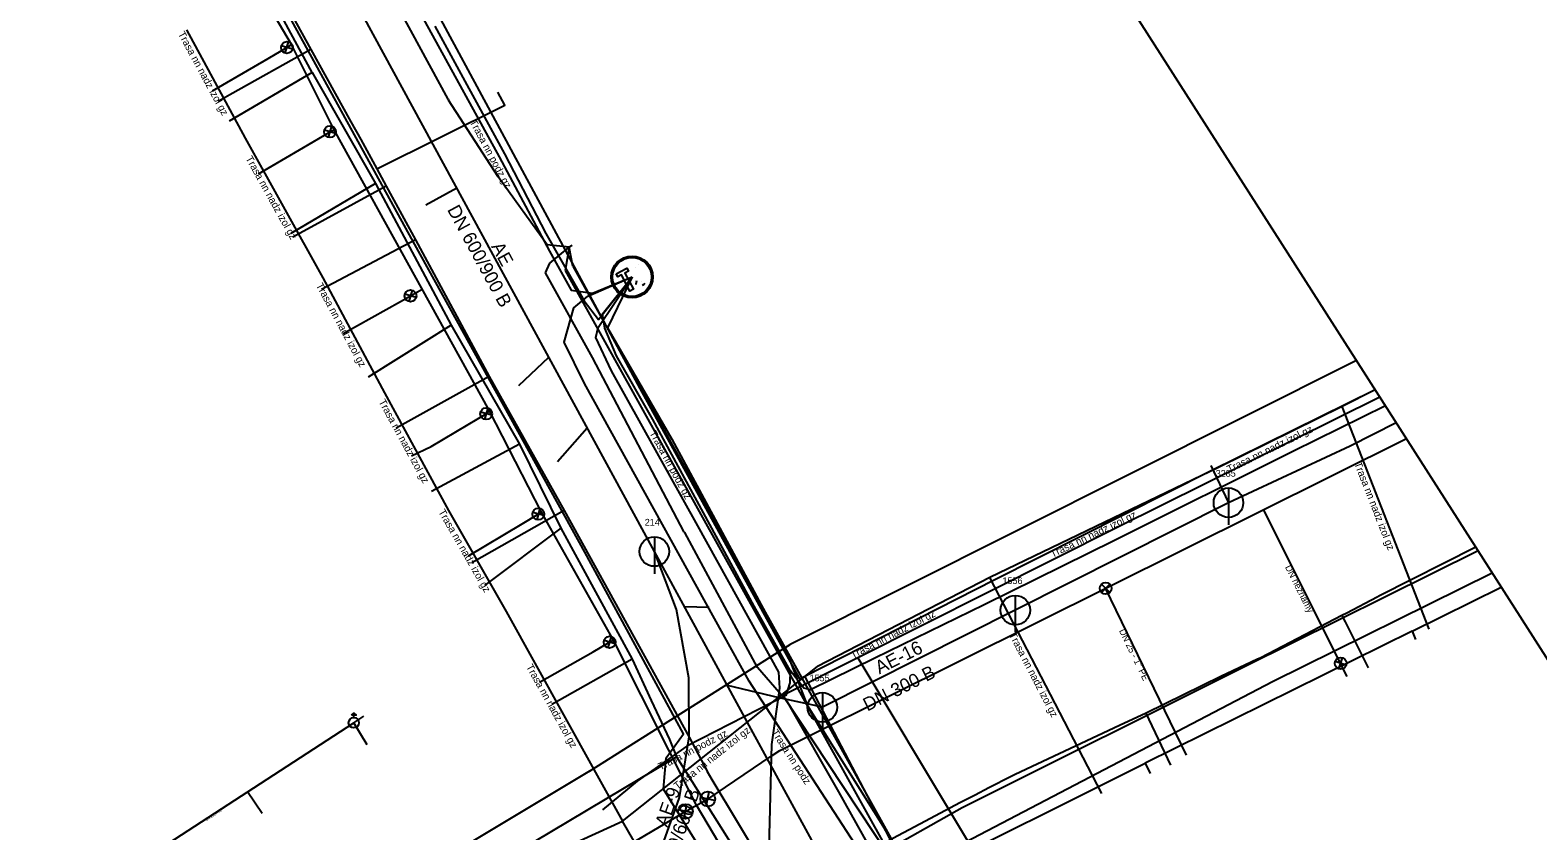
# Model space of a CAD drawing. Extents: x -493753 to -49291, y -1127285 to -112662.
# Drawn here: x -492897.5 to -492795.3, y -1126791 to -1126736.7 of the extents above; entities that cross this region are included whole.
import ezdxf

# ---------------------------------------------------------------- set-up
doc = ezdxf.new("R2010")
doc.units = 0
for name, color, linetype in [('Vrstva 1', 7, 'Continuous'), ('Vrstva 11', 7, 'Continuous'), ('Vrstva 15', 7, 'Continuous'), ('Vrstva 17', 7, 'Continuous'), ('Vrstva 19', 7, 'Continuous'), ('Vrstva 20', 7, 'Continuous'), ('Vrstva 22', 7, 'Continuous'), ('Vrstva 24', 7, 'Continuous'), ('Vrstva 26', 7, 'Continuous'), ('Vrstva 36', 7, 'Continuous'), ('Vrstva 37', 7, 'Continuous'), ('Vrstva 39', 7, 'Continuous'), ('Vrstva 5', 7, 'Continuous'), ('Vrstva 6', 7, 'Continuous'), ('Vrstva 8', 7, 'Continuous'), ('Vrstva 9', 7, 'Continuous')]:
    doc.layers.add(name, color=color, linetype=linetype)

# ---------------------------------------------------------------- blocks, each defined once
blk = doc.blocks.new('_UZAVE')
at = {"layer": 'Vrstva 1'}
for p, q in [((-0.035, -0.035), (0.035, 0.035)), ((0.035, -0.035), (-0.035, 0.035))]:
    blk.add_line(p, q, dxfattribs=at)
for radius in [0.05, 0.0025]:
    blk.add_circle((0, 0), radius, dxfattribs=at)
blk = doc.blocks.new('_UZAV0')
at = {"layer": 'Vrstva 1'}
for p, q in [((-0.035, -0.035), (0.035, 0.035)), ((0.035, -0.035), (-0.035, 0.035))]:
    blk.add_line(p, q, dxfattribs=at)
for radius in [0.05, 0.0025]:
    blk.add_circle((0, 0), radius, dxfattribs=at)
blk = doc.blocks.new('_SACHT')
at = {"layer": 'Vrstva 1'}
blk.add_line((0, 0.035), (0, 0.05), dxfattribs=at)
blk.add_lwpolyline([(-0.015000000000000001, 0.05), (0, 0.065), (0.015000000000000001, 0.05), (0.0025, 0.05)], close=True, dxfattribs=at)
blk.add_circle((0, 0), 0.035, dxfattribs=at)
blk = doc.blocks.new('_SACH0')
at = {"layer": 'Vrstva 1'}
blk.add_line((0, 0.05), (0, -0.075), dxfattribs=at)
blk.add_circle((0, 0), 0.05, dxfattribs=at)

msp = doc.modelspace()

# ---------------------------------------------------------------- linework, layer by layer
at = {"layer": 'Vrstva 1'}
for p, q in [((-492878.44, -1126738.04), (-492883.93000000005, -1126741.12)), ((-492883.93000000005, -1126741.12), (-492884.72000000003, -1126741.56)), ((-492875.73000000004, -1126742.95), (-492875.07, -1126744.1500000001)), ((-492873.34, -1126747.29), (-492879.66000000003, -1126750.75)), ((-492871.36000000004, -1126750.9300000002), (-492877.72000000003, -1126754.3)), ((-492866.38, -1126760.2), (-492872.67000000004, -1126763.7)), ((-492861.29000000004, -1126769.26), (-492867.55000000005, -1126772.82)), ((-492851.27, -1126787.5), (-492851.57, -1126786.98)), ((-492846.86000000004, -1126794.83), (-492851.27, -1126787.5))]:
    msp.add_line(p, q, dxfattribs=at)
for points in [[(-493753.1287883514, -1126773.6344166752), (-493540.8808095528, -1127284.8652782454), (-492737.61000000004, -1126868.6400000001), (-492950.39, -1126535.73)], [(-492937.42000000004, -1126630.24), (-492931.64, -1126641.3), (-492927.73000000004, -1126648.23), (-492923.99000000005, -1126654.85), (-492920.54000000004, -1126661.22), (-492918.14, -1126665.44), (-492916.71, -1126668.03), (-492912.53, -1126675.61), (-492909.26, -1126681.56), (-492909.12, -1126681.82), (-492904.44, -1126690.35), (-492900.54000000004, -1126697.23), (-492897.51, -1126702.99), (-492895.26, -1126707.27), (-492890.45, -1126716.07), (-492886.81, -1126722.78), (-492884.43000000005, -1126727.1600000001), (-492878.44, -1126738.04), (-492875.73000000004, -1126742.95)], [(-492873.98000000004, -1126746.1300000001), (-492865.30000000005, -1126741.81), (-492865.79000000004, -1126740.94)], [(-492875.07, -1126744.1500000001), (-492873.98000000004, -1126746.1300000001), (-492873.34, -1126747.29), (-492871.36000000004, -1126750.9300000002), (-492866.38, -1126760.2), (-492861.29000000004, -1126769.26), (-492852.83, -1126784.62), (-492851.57, -1126786.98)], [(-492799.5317394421, -1126771.7588726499), (-492806.05000000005, -1126775.05), (-492806.22000000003, -1126775.1400000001), (-492808.26, -1126776.22), (-492808.60000000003, -1126776.3900000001), (-492814.09, -1126779.24), (-492814.32, -1126779.34), (-492816.80000000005, -1126780.52), (-492821.87, -1126783), (-492823.68000000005, -1126783.84), (-492830.74000000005, -1126787.1400000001), (-492831.01, -1126787.28), (-492832.52, -1126788.06), (-492833.45, -1126788.55), (-492833.9, -1126788.78), (-492834.48000000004, -1126789.08), (-492836.47000000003, -1126790.12), (-492839.74000000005, -1126791.86)], [(-492808.60000000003, -1126776.3900000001), (-492808.39, -1126776.82), (-492806.83, -1126779.9300000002)], [(-492820.2, -1126786.52), (-492821.67000000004, -1126783.4300000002), (-492821.87, -1126783)]]:
    msp.add_lwpolyline(points, dxfattribs=at)
at = {"layer": 'Vrstva 11'}
for points in [[(-492848.73000000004, -1126797.53), (-492854.56, -1126788.1500000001), (-492854.38, -1126786.02), (-492853.2, -1126784.3900000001), (-492859.9, -1126772.1), (-492871.87, -1126750.4000000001), (-492886.74000000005, -1126723.34), (-492898.4, -1126701.86), (-492908, -1126684.26), (-492916.54000000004, -1126668.6500000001), (-492921.45, -1126660.08), (-492926.55000000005, -1126650.44), (-492932.03, -1126640.6), (-492935.80000000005, -1126632.8900000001)], [(-492806.0331657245, -1126761.5869118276), (-492823.79000000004, -1126770.4000000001), (-492841.39, -1126779.25)], [(-492799.37161551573, -1126772.0093983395), (-492815.12, -1126779.81), (-492834.32, -1126789.4100000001), (-492840.18000000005, -1126792.71), (-492846.28, -1126796.1500000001), (-492848.73000000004, -1126797.53)], [(-492841.39, -1126779.25), (-492846.47000000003, -1126781.81), (-492838.25, -1126794.22), (-492850.91000000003, -1126802.26), (-492877.11000000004, -1126819.04), (-492895.80000000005, -1126830.76), (-492895.54000000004, -1126831.19)], [(-492841.39, -1126779.25), (-492828.07, -1126801.46)]]:
    msp.add_lwpolyline(points, dxfattribs=at)
at = {"layer": 'Vrstva 15'}
for p, q in [((-492855.18000000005, -1126772.05), (-492876.57, -1126732.69)), ((-492870.67000000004, -1126748.56), (-492868.57, -1126747.4100000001)), ((-492864.36000000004, -1126760.8), (-492862.33, -1126758.8900000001)), ((-492861.75, -1126765.95), (-492859.74000000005, -1126763.6700000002)), ((-492817.49000000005, -1126766.21), (-492816.29000000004, -1126768.74)), ((-492816.29000000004, -1126768.74), (-492830.73000000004, -1126776.02)), ((-492848.75, -1126783.83), (-492855.18000000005, -1126772.05)), ((-492851.47000000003, -1126775.83), (-492853.13, -1126775.79)), ((-492830.73000000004, -1126776.02), (-492843.80000000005, -1126782.6)), ((-492891.84, -1126794.23), (-492875.54000000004, -1126783.6400000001)), ((-492875.54000000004, -1126783.6400000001), (-492874.86000000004, -1126783.2)), ((-492874.63, -1126785.1500000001), (-492875.54000000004, -1126783.6400000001)), ((-492841.63, -1126796.85), (-492848.75, -1126783.83)), ((-492881.74000000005, -1126789.79), (-492882.74000000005, -1126788.32))]:
    msp.add_line(p, q, dxfattribs=at)
for points in [[(-492804.924818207, -1126763.3210032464), (-492808.04000000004, -1126764.9000000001), (-492816.29000000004, -1126768.74)], [(-492864.02, -1126803.31), (-492860.16000000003, -1126800.21), (-492856.72000000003, -1126796.26), (-492854.76, -1126792.33), (-492853.47000000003, -1126788.71), (-492852.82, -1126784.59), (-492852.84, -1126780.6), (-492853.67000000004, -1126775.98), (-492855.18000000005, -1126772.05)], [(-492843.80000000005, -1126782.6), (-492846.73000000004, -1126781.95), (-492850.22000000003, -1126781.1300000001)]]:
    msp.add_lwpolyline(points, dxfattribs=at)
at = {"layer": 'Vrstva 20'}
for p, q in [((-492885.12, -1126740.85), (-492881.35000000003, -1126738.6500000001)), ((-492882, -1126746.47), (-492878.30000000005, -1126744.29)), ((-492876.26, -1126757.27), (-492872.38, -1126755.11)), ((-492808.25, -1126780.51), (-492813.91000000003, -1126769.21)), ((-492867.78, -1126772.34), (-492864.14, -1126770.1700000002)), ((-492819.13, -1126785.85), (-492824.61000000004, -1126774.54)), ((-492862.97000000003, -1126780.9000000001), (-492859.33, -1126778.83)), ((-492846.67000000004, -1126785.52), (-492844.52, -1126784.45)), ((-492851.56, -1126788.81), (-492847.26, -1126785.9000000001)), ((-492847.26, -1126785.9000000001), (-492846.67000000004, -1126785.52)), ((-492852.32, -1126789.23), (-492851.56, -1126788.81)), ((-492853.07, -1126789.6500000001), (-492852.32, -1126789.23))]:
    msp.add_line(p, q, dxfattribs=at)
for points in [[(-492852.32, -1126789.23), (-492857.95, -1126778.05), (-492862.82, -1126769.3900000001), (-492866.35000000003, -1126762.51), (-492876.86000000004, -1126743.48), (-492879.77, -1126737.71), (-492881.46, -1126734.83), (-492885.64, -1126727.1400000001), (-492890.48000000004, -1126718.6800000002), (-492890.54000000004, -1126718.22), (-492897.26, -1126705.96), (-492901.5, -1126698.34), (-492906.52, -1126690), (-492906.82, -1126689.4100000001), (-492911.08, -1126681.1), (-492913.41000000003, -1126677.49)], [(-492881.35000000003, -1126738.6500000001), (-492880.07, -1126737.9100000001), (-492879.77, -1126737.71)], [(-492878.30000000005, -1126744.29), (-492877.15, -1126743.61), (-492876.86000000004, -1126743.48)], [(-492872.38, -1126755.11), (-492871.7, -1126754.73), (-492870.9, -1126754.27)], [(-492867.80000000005, -1126763.44), (-492866.57, -1126762.71), (-492866.35000000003, -1126762.51)], [(-492871.63, -1126765.57), (-492870.30000000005, -1126764.9300000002), (-492867.80000000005, -1126763.44)], [(-492844.52, -1126784.45), (-492804.2382379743, -1126764.3952086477)], [(-492864.14, -1126770.1700000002), (-492863.04000000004, -1126769.51), (-492862.82, -1126769.3900000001)], [(-492859.33, -1126778.83), (-492858.21, -1126778.19), (-492857.95, -1126778.05)], [(-492970.22000000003, -1126863.36), (-492958.22000000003, -1126855.33), (-492945.51, -1126848.03), (-492940.77, -1126845.12), (-492925.74000000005, -1126835.49), (-492904.65, -1126823), (-492904.05000000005, -1126822.61), (-492887.33, -1126811.73), (-492869.75, -1126799.77), (-492856.71, -1126791.8), (-492853.07, -1126789.6500000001)], [(-492786.67934407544, -1126894.0659225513), (-492787.42000000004, -1126892.8800000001), (-492788.56, -1126891.12), (-492791.28, -1126887.34), (-492800.45, -1126872.1400000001), (-492806.36000000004, -1126863.49), (-492810.7, -1126856.3), (-492813.24000000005, -1126852.47), (-492818.85000000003, -1126843.1400000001), (-492822.10000000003, -1126837.71), (-492822.55000000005, -1126837.04), (-492834.77, -1126816.78), (-492843.12, -1126804.04), (-492846.14, -1126799.6600000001), (-492852.32, -1126789.23)]]:
    msp.add_lwpolyline(points, dxfattribs=at)
at = {"layer": 'Vrstva 26'}
for p, q in [((-492869.14, -1126741.4100000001), (-492877.07, -1126726.79)), ((-492869.14, -1126741.4100000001), (-492869.12, -1126741.47)), ((-492865.75, -1126746.6600000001), (-492869.12, -1126741.47)), ((-492862.44, -1126751.27), (-492865.75, -1126746.6600000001)), ((-492860.95, -1126751.44), (-492862.44, -1126751.27)), ((-492860.74000000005, -1126751.33), (-492860.95, -1126751.44)), ((-492862.25, -1126752.51), (-492860.95, -1126751.44)), ((-492860.95, -1126751.44), (-492861.22000000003, -1126753.01)), ((-492860.7, -1126752.71), (-492860.95, -1126751.44)), ((-492862.55000000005, -1126753.1600000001), (-492862.25, -1126752.51)), ((-492859.38, -1126758.9100000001), (-492862.55000000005, -1126753.1600000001)), ((-492861.22000000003, -1126753.01), (-492837.7, -1126795.29)), ((-492860.7, -1126752.71), (-492837.9, -1126793.7)), ((-492853.17000000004, -1126770.74), (-492859.38, -1126758.9100000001)), ((-492853.17000000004, -1126770.74), (-492853.12, -1126770.76)), ((-492848.2, -1126779.9100000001), (-492853.12, -1126770.76)), ((-492813.31, -1126780.85), (-492798.4254072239, -1126773.4898109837)), ((-492846.14, -1126782.27), (-492848.2, -1126779.9100000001)), ((-492837.9, -1126793.7), (-492813.31, -1126780.85)), ((-492842.69, -1126788.32), (-492846.14, -1126782.27)), ((-492836.75, -1126798.9000000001), (-492842.69, -1126788.32))]:
    msp.add_line(p, q, dxfattribs=at)
at = {"layer": 'Vrstva 36'}
msp.add_line((-492859.57, -1126786.9300000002), (-492845.99000000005, -1126778.34), dxfattribs=at)
at = {"layer": 'Vrstva 37'}
for p, q in [((-492807.6126526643, -1126759.115688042), (-492845.99000000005, -1126778.34)), ((-492859.57, -1126786.9300000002), (-492899.16000000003, -1126810.62))]:
    msp.add_line(p, q, dxfattribs=at)
at = {"layer": 'Vrstva 39'}
for points in [[(-492879.80000000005, -1126736.94), (-492882.71, -1126731.53)], [(-492872.11000000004, -1126731.46), (-492856.16000000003, -1126761), (-492845.35000000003, -1126780.6700000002), (-492844.99000000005, -1126780.49)], [(-492878.37, -1126739.61), (-492879.80000000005, -1126736.94)], [(-492878.37, -1126739.61), (-492883.98000000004, -1126742.8900000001)], [(-492878.37, -1126739.61), (-492874.08, -1126747.12)], [(-492874.08, -1126747.12), (-492879.80000000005, -1126750.5)], [(-492874.08, -1126747.12), (-492868.95, -1126756.71)], [(-492868.95, -1126756.71), (-492874.57, -1126760.24)], [(-492868.95, -1126756.71), (-492864.31, -1126764.78)], [(-492844.99000000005, -1126780.49), (-492832.11000000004, -1126773.94), (-492817.5, -1126766.59), (-492806.3601976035, -1126761.0752463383)], [(-492864.31, -1126764.78), (-492870.28, -1126767.99)], [(-492864.31, -1126764.78), (-492861.52, -1126770.46)], [(-492861.52, -1126770.46), (-492866.68000000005, -1126774.34)], [(-492861.52, -1126770.46), (-492856.69, -1126779.34)], [(-492803.85000000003, -1126777.45), (-492797.80753528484, -1126774.4565171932)], [(-492803.85000000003, -1126777.45), (-492821.94, -1126786.3900000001)], [(-492803.85000000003, -1126777.45), (-492803.62, -1126778.01)], [(-492856.69, -1126779.34), (-492862.13, -1126782.4000000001)], [(-492856.69, -1126779.34), (-492855.39, -1126782.1400000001)], [(-492837.75, -1126794.28), (-492844.99000000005, -1126780.49)], [(-492855.39, -1126782.1400000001), (-492854.16000000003, -1126784.79), (-492853.69, -1126785.96)], [(-492870.58, -1126796.02), (-492853.69, -1126785.96)], [(-492853.69, -1126785.96), (-492845.76, -1126798.53), (-492841.59, -1126804.98)], [(-492837.75, -1126794.28), (-492821.94, -1126786.3900000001)], [(-492821.94, -1126786.3900000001), (-492821.59, -1126787.09)]]:
    msp.add_lwpolyline(points, dxfattribs=at)
at = {"layer": 'Vrstva 5'}
for points in [[(-492872.37, -1126733.1400000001), (-492870.46, -1126736.6500000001), (-492865.7, -1126745.32), (-492862.28, -1126751.7), (-492860.81, -1126754.35), (-492859.38, -1126754.54), (-492856.69, -1126753.45)], [(-492886.87, -1126736.71), (-492882.91000000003, -1126744.04)], [(-492882.91000000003, -1126744.04), (-492877.64, -1126753.52)], [(-492877.64, -1126753.52), (-492873.46, -1126761.3)], [(-492863.25, -1126810.8800000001), (-492864.13, -1126809.3800000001), (-492840.13, -1126794.11), (-492848.76, -1126780.82), (-492859.92000000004, -1126760.6700000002), (-492861.29000000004, -1126757.87), (-492860.64, -1126755.54), (-492859.68000000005, -1126754.76), (-492856.69, -1126753.45)], [(-492845.99000000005, -1126780.1), (-492848.42000000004, -1126775.75), (-492855.28, -1126763.11), (-492857.74000000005, -1126758.79), (-492858.54000000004, -1126756.9200000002), (-492858.7, -1126755.94), (-492856.69, -1126753.45)], [(-492873.46, -1126761.3), (-492869.13, -1126769.26)], [(-492806.3447955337, -1126761.099344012), (-492808.58, -1126762.23)], [(-492805.6584604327, -1126762.1731658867), (-492811.88, -1126765.25), (-492824.02, -1126771.29), (-492832.84, -1126775.6500000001), (-492840.24000000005, -1126779.28), (-492844.61000000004, -1126781.4100000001), (-492845.05000000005, -1126781.31), (-492845.99000000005, -1126780.1)], [(-492808.58, -1126762.23), (-492816.93000000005, -1126766.34)], [(-492802.7, -1126777.31), (-492808.58, -1126762.23)], [(-492816.93000000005, -1126766.34), (-492832.46, -1126773.8)], [(-492869.13, -1126769.26), (-492865.21, -1126776.11)], [(-492832.46, -1126773.8), (-492844.12, -1126779.84)], [(-492824.87, -1126788.44), (-492832.46, -1126773.8)], [(-492865.21, -1126776.11), (-492857.33, -1126790.3)], [(-492857.33, -1126790.3), (-492844.12, -1126779.84)], [(-492845.99000000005, -1126780.1), (-492846.01, -1126780.95), (-492846.28, -1126781.8), (-492847.16000000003, -1126782.24), (-492852.99000000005, -1126785.24), (-492856.35000000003, -1126787.59), (-492858.69, -1126789.54)], [(-492873.51, -1126797.69), (-492857.33, -1126790.3)], [(-492850.08, -1126802.8800000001), (-492857.33, -1126790.3)]]:
    msp.add_lwpolyline(points, dxfattribs=at)
at = {"layer": 'Vrstva 6'}
for points in [[(-492870.04000000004, -1126736.47), (-492865.33, -1126745.11), (-492862.54000000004, -1126750.51), (-492859.93000000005, -1126755.07), (-492858.96, -1126756.34), (-492856.69, -1126753.45)], [(-492898.47000000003, -1126832.09), (-492886.41000000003, -1126824.24), (-492876.05000000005, -1126817.81), (-492860.04000000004, -1126807.6800000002), (-492849.41000000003, -1126801.1300000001), (-492848.23000000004, -1126800.02), (-492847.80000000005, -1126798.34), (-492847.4, -1126792.12), (-492847.23000000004, -1126785.11), (-492846.68000000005, -1126781.31), (-492846.74000000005, -1126780.22), (-492852.23000000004, -1126770.3), (-492858.08, -1126759.81), (-492859.14, -1126757.56), (-492858.99000000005, -1126756.8800000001), (-492856.69, -1126753.45)], [(-492856.69, -1126753.45), (-492858.36000000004, -1126756.9000000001), (-492854, -1126764.44), (-492846.25, -1126778.79), (-492844.82, -1126782.46), (-492836.75, -1126795.34), (-492826.22000000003, -1126812.12), (-492807.54000000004, -1126842.09), (-492794.08, -1126863.74), (-492778.1241839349, -1126889.6329544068)]]:
    msp.add_lwpolyline(points, dxfattribs=at)
at = {"layer": 'Vrstva 8'}
msp.add_lwpolyline([(-492857.76795837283, -1126753.2292562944), (-492857.0524047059, -1126752.8499103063), (-492856.938450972, -1126753.0648592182), (-492857.1761743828, -1126753.1908867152), (-492856.5989087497, -1126754.2797727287), (-492856.8335073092, -1126754.4041435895), (-492857.41077294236, -1126753.3152575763), (-492857.6540046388, -1126753.4442052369)], close=True, dxfattribs=at)
for points in [[(-492856.4899527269, -1126752.7947227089), (-492856.4874678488, -1126752.7934053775)], [(-492856.22951841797, -1126752.5834395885), (-492856.2334704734, -1126752.5759848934)], [(-492856.3875155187, -1126753.714502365), (-492856.44382650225, -1126753.9385358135), (-492856.43723975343, -1126753.950960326)], [(-492856.0444755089, -1126753.7491055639), (-492856.0544151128, -1126753.754374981)], [(-492855.9895033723, -1126753.996908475), (-492855.87037791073, -1126753.9273883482), (-492855.8125070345, -1126753.874425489)]]:
    msp.add_lwpolyline(points, dxfattribs=at)
for radius in [1.4115987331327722, 1.3204111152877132]:
    msp.add_circle((-492856.69, -1126753.45), radius, dxfattribs=at)

# ---------------------------------------------------------------- block references
at = {"layer": 'Vrstva 17'}
for name, p, xscale, yscale in [('_SACH0', (-492816.29000000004, -1126768.74), 19.997500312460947, 19.997500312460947), ('_SACH0', (-492855.18000000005, -1126772.05), 19.997500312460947, 19.997500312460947), ('_SACH0', (-492830.73000000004, -1126776.02), 19.997500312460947, 19.997500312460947), ('_SACH0', (-492843.80000000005, -1126782.6), 19.997500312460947, 19.997500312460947), ('_SACHT', (-492875.54000000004, -1126783.6400000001), 9.998750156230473, 9.998750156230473)]:
    msp.add_blockref(name, p, dxfattribs=dict(at, xscale=xscale, yscale=yscale))
at = {"layer": 'Vrstva 22'}
for name, p, xscale, yscale, rotation in [('_UZAV0', (-492880.07, -1126737.9100000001), 7.999000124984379, 7.999000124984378, 28.542533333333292), ('_UZAV0', (-492877.15, -1126743.61), 7.999000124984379, 7.999000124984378, 28.542533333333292), ('_UZAV0', (-492871.7, -1126754.73), 7.99900012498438, 7.999000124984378, 119.19454166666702), ('_UZAV0', (-492866.57, -1126762.71), 7.999000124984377, 7.999000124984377, 119.447713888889), ('_UZAV0', (-492863.04000000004, -1126769.51), 7.999000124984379, 7.999000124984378, 119.39408888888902), ('_UZAV0', (-492858.21, -1126778.19), 7.99900012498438, 7.999000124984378, 118.82552222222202), ('_UZAV0', (-492808.69, -1126779.62), 7.999000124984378, 7.999000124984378, 26.628288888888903), ('_UZAVE', (-492851.56, -1126788.81), 9.998750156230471, 9.998750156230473, 33.2741916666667), ('_UZAVE', (-492853.07, -1126789.6500000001), 9.998750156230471, 9.998750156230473, 33.2741916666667)]:
    msp.add_blockref(name, p, dxfattribs=dict(at, xscale=xscale, yscale=yscale, rotation=rotation))
at = {"layer": 'Vrstva 22', "xscale": 7.999000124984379, "yscale": 7.999000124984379}
msp.add_blockref('_UZAV0', (-492824.61000000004, -1126774.54), dxfattribs=at)

# ---------------------------------------------------------------- texts
at = {"layer": 'Vrstva 19'}
for s, height, rotation, p in [('DN 600/900 B', 0.9098880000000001, 298.5275916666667, (-492869.238, -1126748.886)), ('AE', 0.9098880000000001, 298.5275916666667, (-492866.25600000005, -1126751.385)), ('AE-16', 0.9098880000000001, 26.74140277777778, (-492839.939, -1126780.3760000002)), ('DN 300 B', 0.9098880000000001, 26.74140277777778, (-492840.75100000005, -1126782.8900000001)), ('DN 500/600 B', 0.9098880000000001, 70.41438611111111, (-492854.639, -1126795.5150000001)), ('AE-9', 0.9098880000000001, 70.41438611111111, (-492854.30500000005, -1126790.764)), ('DN 200 PVC', 0.16049400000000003, 33.01069444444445, (-492885.50700000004, -1126790.306))]:
    msp.add_text(s, height=height, rotation=rotation, dxfattribs=at).set_placement(p)
for s, p in [('3285', (-492817.152, -1126766.98)), ('214', (-492855.829, -1126770.29)), ('1556', (-492831.59300000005, -1126774.25)), ('1555', (-492844.663, -1126780.84))]:
    msp.add_text(s, height=0.45494400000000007, dxfattribs=at).set_placement(p)
at = {"layer": 'Vrstva 24'}
for s, rotation, p in [('DN neznámý', 296.6278972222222, (-492812.471, -1126773.101)), ("DN 25 - 1'' PE", 295.83617777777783, (-492823.715, -1126777.415))]:
    msp.add_text(s, height=0.45499800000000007, rotation=rotation, dxfattribs=at).set_placement(p)
at = {"layer": 'Vrstva 9'}
for s, height, rotation, p in [('Trasa nn nadz izol gz', 0.49999800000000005, 298.38226944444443, (-492887.46300000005, -1126736.982)), ('Trasa nn podz gz', 0.49999800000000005, 298.20425555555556, (-492867.704, -1126742.95)), ('Trasa nn nadz izol gz', 0.49999800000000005, 299.0717916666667, (-492882.885, -1126745.419)), ('Trasa nn nadz izol gz', 0.49999800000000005, 298.24726111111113, (-492878.11500000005, -1126754.017)), ('Trasa nn nadz izol gz', 0.49999800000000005, 298.54422500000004, (-492873.873, -1126761.898)), ('Trasa nn nadz izol gz', 0.499998, 26.209211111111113, (-492816.237, -1126766.73)), ('Trasa nn podz gz', 0.49999800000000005, 298.48993611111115, (-492855.52800000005, -1126764.019)), ('Trasa nn nadz izol gz', 0.49999800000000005, 291.3037555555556, (-492807.77800000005, -1126766.092)), ('Trasa nn nadz izol gz', 0.49999800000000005, 299.77819444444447, (-492869.82700000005, -1126769.3560000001)), ('Trasa nn nadz izol gz', 0.49999800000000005, 25.657044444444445, (-492828.207, -1126772.475)), ('Trasa nn nadz izol gz', 0.49999800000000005, 27.38415555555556, (-492841.72500000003, -1126779.3320000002)), ('Trasa nn nadz izol gz', 0.49999800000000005, 297.4069194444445, (-492831.174, -1126777.686)), ('Trasa nn nadz izol gz', 0.49999800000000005, 299.0504055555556, (-492863.884, -1126779.848)), ('Trasa nn nadz izol gz', 0.49999800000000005, 38.38017777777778, (-492853.619, -1126788.1940000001)), ('Trasa nn podz', 0.49999800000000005, 302.97256111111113, (-492847.275, -1126784.296)), ('Trasa nn podz gz', 0.49999800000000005, 27.20546388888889, (-492854.772, -1126786.8830000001))]:
    msp.add_text(s, height=height, rotation=rotation, dxfattribs=at).set_placement(p)

doc.saveas('drawing.dxf')
